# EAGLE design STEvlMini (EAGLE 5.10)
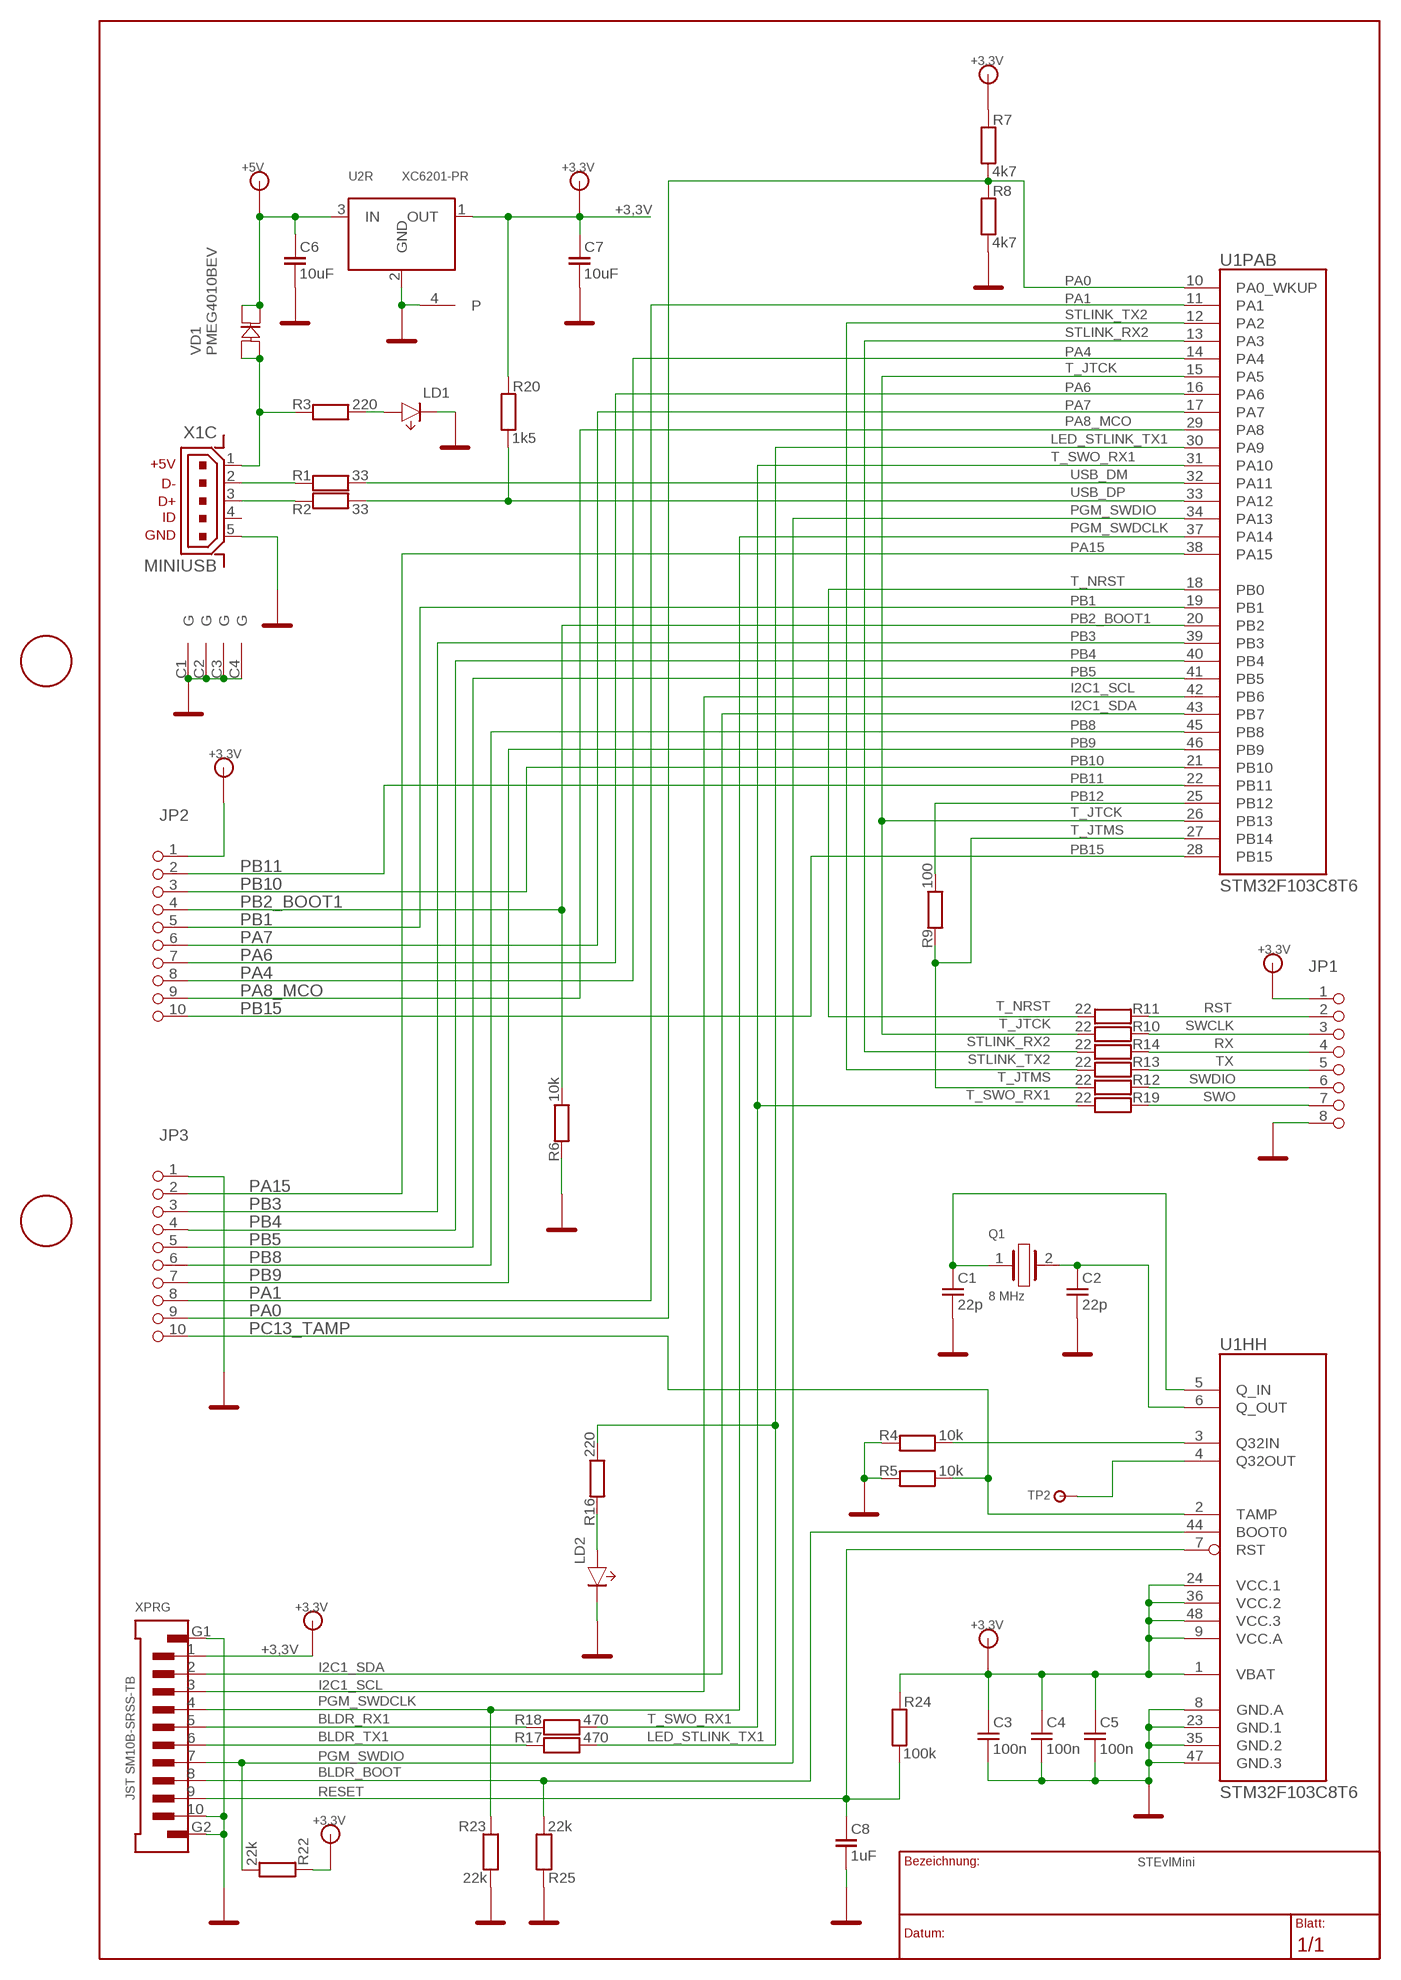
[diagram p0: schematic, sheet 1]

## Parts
C1  22p  SMD-0603  [SOT-0603]
C2  22p  SMD-0603  [SOT-0603]
C3  100n  SMD-0603  [SOT-0603]
C4  100n  SMD-0603  [SOT-0603]
C5  100n  SMD-0603  [SOT-0603]
C6  10uF  SMD-0805  [SOT-0805]
C7  10uF  SMD-0805  [SOT-0805]
C8  1uF  SMD-0805  [SOT-0805]
JP1  PINHD-1X8  [1X08]
JP2  PINHD-1X10'GERADE'  [1X10]
JP3  PINHD-1X10'GERADE'  [1X10]
LD1  LED0805  [LED0805]
LD2  LED0805  [LED0805]
Q1  8 MHz  XTAL'SMD5X3'  [XTAL5X3]
R1  33  SMD-0603  [SMD-0603]
R2  33  SMD-0603  [SMD-0603]
R3  220  SMD-0603  [SMD-0603]
R4  10k  SMD-0603  [SMD-0603]
R5  10k  SMD-0603  [SMD-0603]
R6  10k  SMD-0603  [SMD-0603]
R7  4k7  SMD-0603  [SMD-0603]
R8  4k7  SMD-0603  [SMD-0603]
R9  100  SMD-0603  [SMD-0603]
R10  22  SMD-0603  [SMD-0603]
R11  22  SMD-0603  [SMD-0603]
R12  22  SMD-0603  [SMD-0603]
R13  22  SMD-0603  [SMD-0603]
R14  22  SMD-0603  [SMD-0603]
R16  220  SMD-0603  [SMD-0603]
R17  470  SMD-0603  [SMD-0603]
R18  470  SMD-0603  [SMD-0603]
R19  22  SMD-0603  [SMD-0603]
R20  1k5  SMD-0603  [SMD-0603]
R22  22k  SMD-0603  [SMD-0603]
R23  22k  SMD-0603  [SMD-0603]
R24  100k  SMD-0603  [SMD-0603]
R25  22k  SMD-0603  [SMD-0603]
TP2  TESTPAD  [TESTPAD]
U1  STM32F103C8T6  [LQFP48]
U2  XC6201-PR  [SOT89]
VD1  PMEG4010BEV  [SOT23-6]
X1  MINIUSB  [UX60A-MB-5SY]
XPRG  JST SM10B-SRSS-TB  SR-10'H'  [SR-10H]

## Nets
+3,3V: C3.2 C4.2 C5.2 C7.2 JP1.1 JP2.1 R7.2 R20.2 R22.2 R24.2 U1.1(HH:VBAT) U1.9(HH:VCC.A) U1.24(HH:VCC.1) U1.36(HH:VCC.2) U1.48(HH:VCC.3) U2.1(R:OUT) XPRG.1
+5V: C6.2 U2.3(R:IN) VD1.1(K1) VD1.6(K)
BLDR_BOOT: R25.1 U1.44(HH:BOOT0) XPRG.8
BLDR_RX1: R18.1 XPRG.5
BLDR_TX1: R17.1 XPRG.6
GND: C1.1 C2.1 C3.1 C4.1 C5.1 C6.1 C7.1 C8.1 JP1.8 JP3.1 LD1.K LD2.K R4.2 R5.2 R6.2 R8.1 R23.1 R25.2 U1.8(HH:GND.A) U1.23(HH:GND.1) U1.35(HH:GND.2) U1.47(HH:GND.3) U2.2(R:GND) U2.4(P) X1.5 X1.C1(G) X1.C2(G) X1.C3(G) X1.C4(G) XPRG.10 XPRG.G1 XPRG.G2
I2C1_SCL: U1.42(PAB:PB6) XPRG.3
I2C1_SDA: U1.43(PAB:PB7) XPRG.2
LED_STLINK_TX1: R16.1 R17.2 U1.30(PAB:PA9)
N$1: R1.2 X1.2
N$2: R2.2 X1.3
N$4: C2.2 Q1.2 U1.6(HH:Q_OUT)
N$5: C1.2 Q1.1 U1.5(HH:Q_IN)
N$6: R4.1 U1.3(HH:Q32IN)
N$8: LD1.A R3.1
N$15: LD2.A R16.2
N$25: TP2.P$1(T) U1.4(HH:Q32OUT)
PA0: JP3.9 R7.1 R8.2 U1.10(PAB:PA0_WKUP)
PA1: JP3.8 U1.11(PAB:PA1)
PA4: JP2.8 U1.14(PAB:PA4)
PA6: JP2.7 U1.16(PAB:PA6)
PA7: JP2.6 U1.17(PAB:PA7)
PA8_MCO: JP2.9 U1.29(PAB:PA8)
PA15: JP3.2 U1.38(PAB:PA15)
PB1: JP2.5 U1.19(PAB:PB1)
PB2_BOOT1: JP2.4 R6.1 U1.20(PAB:PB2)
PB3: JP3.3 U1.39(PAB:PB3)
PB4: JP3.4 U1.40(PAB:PB4)
PB5: JP3.5 U1.41(PAB:PB5)
PB8: JP3.6 U1.45(PAB:PB8)
PB9: JP3.7 U1.46(PAB:PB9)
PB10: JP2.3 U1.21(PAB:PB10)
PB11: JP2.2 U1.22(PAB:PB11)
PB12: R9.1 U1.25(PAB:PB12)
PB15: JP2.10 U1.28(PAB:PB15)
PC13_TAMP: JP3.10 R5.1 U1.2(HH:TAMP)
PGM_SWDCLK: R23.2 U1.37(PAB:PA14) XPRG.4
PGM_SWDIO: R22.1 U1.34(PAB:PA13) XPRG.7
RESET: C8.2 R24.1 U1.7(HH:RST) XPRG.9
RST: JP1.2 R11.2
RX: JP1.4 R14.2
STLINK_RX2: R14.1 U1.13(PAB:PA3)
STLINK_TX2: R13.1 U1.12(PAB:PA2)
SWCLK: JP1.3 R10.2
SWDIO: JP1.6 R12.2
SWO: JP1.7 R19.2
T_JTCK: R10.1 U1.15(PAB:PA5) U1.26(PAB:PB13)
T_JTMS: R9.2 R12.1 U1.27(PAB:PB14)
T_NRST: R11.1 U1.18(PAB:PB0)
T_SWO_RX1: R18.2 R19.1 U1.31(PAB:PA10)
TX: JP1.5 R13.2
USB_DM: R1.1 U1.32(PAB:PA11)
USB_DP: R2.1 R20.1 U1.33(PAB:PA12)
USB_V5V: R3.2 VD1.3(A1) VD1.4(A) X1.1
Unconnected: X1.4

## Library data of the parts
C1-C5 = C_KERAM:SMD-0603
C6-C8 = C_KERAM:SMD-0805
JP1 = PINHD-Q:PINHD-1X8
JP2 JP3 = PINHD-Q:PINHD-1X10
LD1 LD2 = DIODEN:LED0805
Q1 = Z_SPECIA:XTAL
R1-R14 R16-R20 R22-R25 = R:SMD-0603
TP2 = Z_CONNEC:TESTPAD
U1 = SGS:STM32F103C8T6
U2 = TOREX:XC6201-PR
VD1 = DIODEN:PMEG4010BEV: Schottky, 40V, 1A
X1 = mini-usb:MINIUSB
XPRG = JST:SR-10

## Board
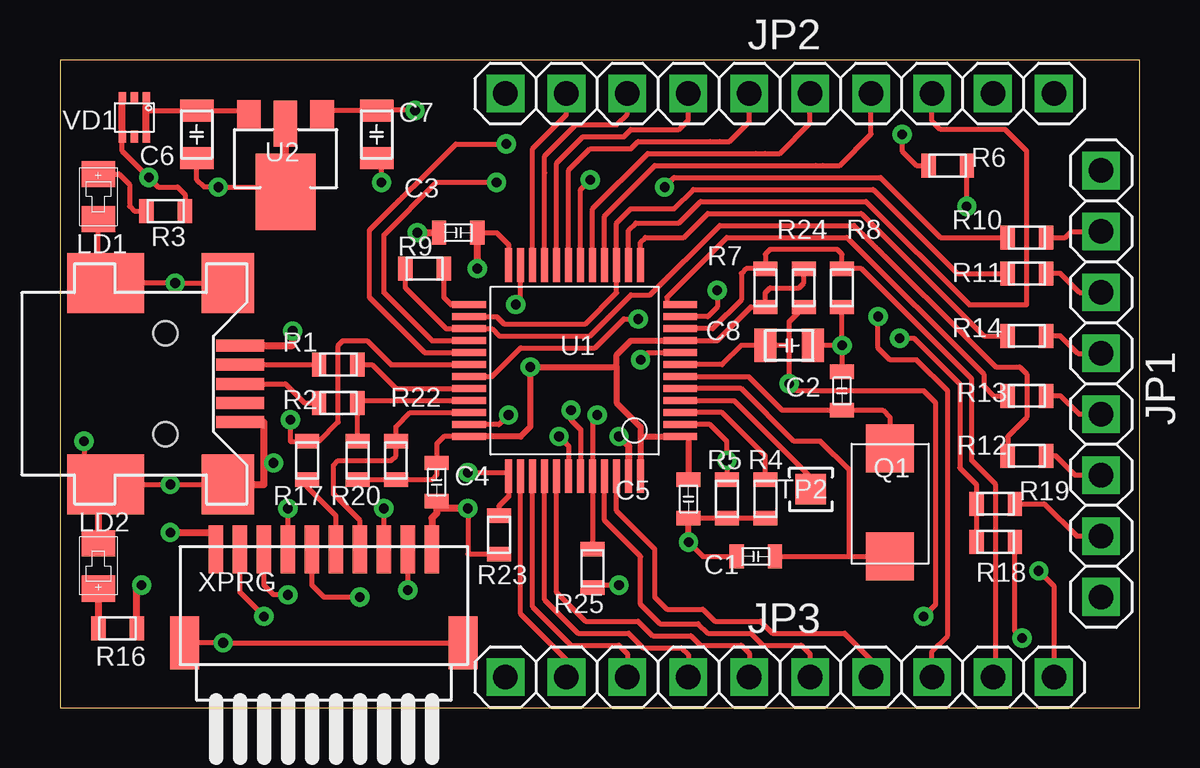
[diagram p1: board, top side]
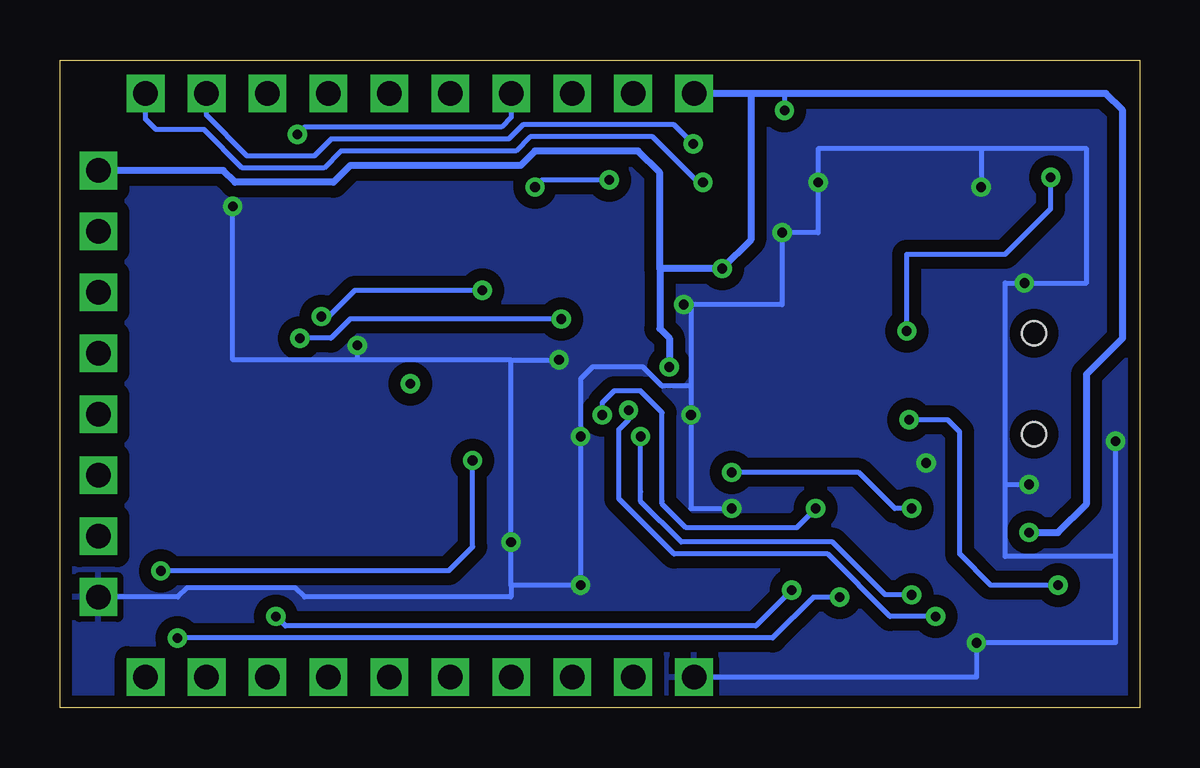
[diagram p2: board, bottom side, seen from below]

Size 45 x 27 mm. Coordinates in mm from the lower left corner, seen from the top.
Outline: 0,0 45,0 45,27 0,27 0,0
Copper layers (1*16): Top 0.035mm / dielectric 1.5mm / Bottom 0.035mm
Design rules "default *": minimum track width 0.15mm, minimum drill 0.3mm, track to track 0.15mm, track to pad 0.15mm, pad to pad 0.15mm, via to via 0.15mm, smd to smd 0mil, copper to edge 0.15mm, drill to drill 0.15mm, minimum pad ring 0.15mm, minimum via ring 0.15mm, stop-mask expansion 4mil, vias tented up to drill 0mil, thermal gap 10mil

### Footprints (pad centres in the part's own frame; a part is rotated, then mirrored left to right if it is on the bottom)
SOT-0603 = smd 0.6 x 1: 1 -0.8,0; 2 0.8,0
SOT-0805 = smd 0.914 x 1.397: 1 -0.991,0; 2 0.991,0
1X08 = drill 1.016 pad 1.575 square: 1 -8.89,0; 2 -6.35,0; 3 -3.81,0; 4 -1.27,0; 5 1.27,0; 6 3.81,0; 7 6.35,0; 8 8.89,0
1X10 = drill 1.016 pad 1.575 square: 1 -11.43,0; 2 -8.89,0; 3 -6.35,0; 4 -3.81,0; 5 -1.27,0; 6 1.27,0; 7 3.81,0; 8 6.35,0; 9 8.89,0; 10 11.43,0
LED0805 = smd 1.092 x 1.397: A 0.94,0; K -0.94,0
XTAL5X3 = smd 2 x 2: 1 -2.2,0; 2 2.3,0
SMD-0603 = smd 0.6 x 1: 1 -0.8,0; 2 0.8,0
TESTPAD = smd 1.27 x 1.27: P$1 0,0
LQFP48 = smd 0.28 x 1.4: 1 -2.75,-4.4; 2 -2.25,-4.4; 3 -1.75,-4.4; 4 -1.25,-4.4; 5 -0.75,-4.4; 6 -0.25,-4.4; 7 0.25,-4.4; 8 0.75,-4.4; 9 1.25,-4.4; 10 1.75,-4.4; 11 2.25,-4.4; 12 2.75,-4.4; 25 2.75,4.4; 26 2.25,4.4; 27 1.75,4.4; 28 1.25,4.4; 29 0.75,4.4; 30 0.25,4.4; 31 -0.25,4.4; 32 -0.75,4.4; 33 -1.25,4.4; 34 -1.75,4.4; 35 -2.25,4.4; 36 -2.75,4.4 | smd 1.4 x 0.28: 13 4.4,-2.75; 14 4.4,-2.25; 15 4.4,-1.75; 16 4.4,-1.25; 17 4.4,-0.75; 18 4.4,-0.25; 19 4.4,0.25; 20 4.4,0.75; 21 4.4,1.25; 22 4.4,1.75; 23 4.4,2.25; 24 4.4,2.75; 37 -4.4,2.75; 38 -4.4,2.25; 39 -4.4,1.75; 40 -4.4,1.25; 41 -4.4,0.75; 42 -4.4,0.25; 43 -4.4,-0.25; 44 -4.4,-0.75; 45 -4.4,-1.25; 46 -4.4,-1.75; 47 -4.4,-2.25; 48 -4.4,-2.75
SOT89 = smd 0.991 x 1.194: 1 -1.524,-1.829; 3 1.524,-1.829 | smd 0.991 x 1.905: 2 0,-1.448 | smd 2.5 x 3.2: 4 0,1.4
SOT23-6 = smd 0.3 x 0.5: 1 -0.5,-0.8; 2 0,-0.8; 3 0.5,-0.8; 4 0.5,0.8; 5 0,0.8; 6 -0.5,0.8
UX60A-MB-5SY = smd 0.5 x 2: 1 -1.6,3.1; 2 -0.8,3.1; 3 0,3.1; 4 0.8,3.1; 5 1.6,3.1 | smd 2.5 x 2.2: C1 -4.2,2.6; C4 4.2,2.6 | smd 2.5 x 3.2: C2 -4.2,-2.5; C3 4.2,-2.5 | hole 1.016: -2.1,0; 2.1,0
SR-10H = smd 0.6 x 2: 1 -4.5,2.4; 2 -3.5,2.4; 3 -2.5,2.4; 4 -1.5,2.4; 5 -0.5,2.4; 6 0.5,2.4; 7 1.5,2.4; 8 2.5,2.4; 9 3.5,2.4; 10 4.5,2.4 | smd 1.2 x 2.2: G1 -5.8,-1.5; G2 5.8,-1.5

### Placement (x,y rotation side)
C1  29,6.3 0 top
C2  32.6,13.2 270 top
C3  16.6,19.8 0 top
C4  15.7,9.4 90 top
C5  26.2,8.7 90 top
C6  5.7,23.9 90 top
C7  13.2,23.9 90 top
C8  30.4,15.1 180 top
JP1  43.4,13.5 270 top
JP2  30,25.6 0 top
JP3  30,1.27 0 top
LD1  1.6,21.3 90 top
LD2  1.6,5.9 270 top
Q1  34.6,8.5 90 top
R1  11.6,14.3 180 top
R2  11.6,12.7 180 top
R3  4.41,20.7 0 top
R4  29.4,8.7 270 top
R5  27.8,8.7 270 top
R6  37,22.6 0 top
R7  29.4,17.5 270 top
R8  32.6,17.5 90 top
R9  15.2,18.3 180 top
R10  40.3,18.1 0 top
R11  40.3,19.6 0 top
R12  40.3,10.5 0 top
R13  40.3,13 0 top
R14  40.3,15.5 0 top
R16  2.4,3.3 180 top
R17  10.3,10.3 90 top
R18  39,6.9 180 top
R19  39,8.5 0 top
R20  12.4,10.3 270 top
R22  14,10.3 270 top
R23  18.3,7.2 90 top
R24  31,17.5 90 top
R25  22.2,5.8 270 top
TP2  31.3,9.1 0 top
U1  21.45,14.05 90 top
U2  9.4,22.9 180 top
VD1  3.1,24.6 180 top
X1  4.4,13.5 270 top
XPRG  11,4.2 0 top

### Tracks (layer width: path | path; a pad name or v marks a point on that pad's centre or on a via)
+3,3V  (via drill 0.4 pad 0.8)
  Top 0.2: U1.9 27.4,15.3 28.8,16.7 R7.2 29.4,17.3 29.6,17.5 30.8,17.5 31,17.7 R24.2 | R20.2 R22.2 15.5,9.5 15.7,9.7 C4.2 15.7,11 16,11.3 U1.36 | U1.24 18.7,19.3 18.2,19.8 C3.2 | U2.1 10.92,24.89 C7.2 v14.8,24.9
  Top 0.25: 24.2,11.3 24.2,11.7 23.2,12.7 23.2,14.2 | 24.2,11.3 U1.1 26.2,11.3 C5.2 | 23.2,14.2 23.2,14.7 23.8,15.3 U1.9 | 24.2,11.3 U1.48 | U1.36 19.2,11.3 19.6,11.7 19.6,12.4 v19.6,14.2 23.2,14.2
  Top 0.3: XPRG.1 6.5,7.3 v4.6,7.3 | v17.4,18.3 C3.2
  Bottom 0.2: 14.8,25.6 v14.8,24.9
  Bottom 0.3: v4.6,7.3 3.4,7.3 2.2,8.5 2.2,13.9 0.7,15.4 0.7,24.9 1.4,25.6 14.8,25.6 16.2,25.6 | 20,18.3 20,15.8 19.6,15.4 v19.6,14.2 | 20,18.3 v17.4,18.3 16.2,19.5 16.2,25.6 | 16.2,25.6 JP2.1 | JP1.1 38.19,22.39 37.7,21.9 33.6,21.9 32.9,22.6 25.8,22.6 25.2,23.2 20.9,23.2 20,22.3 20,18.3
+5V
  Top 0.2: U2.3 7.88,24.89 C6.2 3.6,24.89 VD1.1
  Top 0.3: VD1.6 VD1.1
BLDR_BOOT  (via drill 0.4 pad 0.8)
  Top 0.2: R25.1 U1.44 22.2,12 v22.4,12.2 | XPRG.8 v13.5,8.3
  Bottom 0.2: v13.5,8.3 14.3,7.5 18.9,7.5 19.9,8.5 19.9,8.6 19.9,12.3 20.8,13.2 21.9,13.2 22.4,12.7 v22.4,12.2
BLDR_RX1  (via drill 0.4 pad 0.8)
  Top 0.2: XPRG.5 10.5,5.1 11,4.6 v12.5,4.6 | v40.1,2.9 39.8,3.2 R18.1
  Bottom 0.2: v12.5,4.6 13.6,4.6 15.3,2.9 v40.1,2.9
BLDR_TX1
  Top 0.2: XPRG.6 11.5,8 10.3,9.2 R17.1
GND  (via drill 0.4 pad 0.8)
  Top 0.2: C5.1 R5.2 R4.2 | U1.8 24.5,14.8 v24.2,14.5 | v32.6,15.1 C8.1 | v32.6,15.1 R8.1 | C1.1 26.8,6.3 v26.2,6.9 | X1.C3 1.6,9.3 1.6,8.75 | XPRG.G1 v6.8,2.7 XPRG.G2 | v1,11.1 1,9.3 X1.C3 | 1.6,17.7 LD1.K | X1.C1 v4.8,17.7 X1.C2 | X1.C3 v4.6,9.3 X1.C4 | 8.5,11.9 X1.5 | U1.35 18.3,11.8 v18.7,12.2 | U1.23 19.2,17 v19,16.8 | R25.2 22.2,5.1 v23.3,5.1 | v32.6,15.1 C2.1 | R23.1 17,6.4 v17,8.3 | C6.1 5.7,22 6,21.7 v6.6,21.7 9.4,21.7 U2.4 | v37.8,20.9 R6.2 | C7.1 13.4,22.71 v13.4,21.9
  Top 0.25: v26.2,6.9 C5.1
  Top 0.3: 1.6,8.75 LD2.K | X1.C2 1.6,17.7 | X1.C4 8.5,9.3 8.5,10.2 | 8.5,10.2 8.5,11.9 | U2.4 U2.2 | v14.9,19.8 C3.1 | XPRG.10 15.5,7.9 15.7,8.1 15.7,8.3 | 8.5,10.2 v8.9,10.2 | U1.47 23.7,10.9 v23.3,11.3 | 15.7,8.3 C4.1 | v17,8.3 15.7,8.3
  Bottom 0.2: 26.2,14.5 v24.2,14.5 | 26.2,14.5 C5.1 v26.2,6.9 26.2,5.1 | 26.2,14.5 32.6,14.5 | 1,6.3 1,2.7 v6.8,2.7 6.8,1.27 JP3.1 | 1,6.3 v1,11.1 | 5.6,9.3 v4.6,9.3 | 5.6,9.3 5.6,6.3 1,6.3 | 5.6,9.3 5.6,17.7 v4.8,17.7 2.2,17.7 2.2,23.3 6.6,23.3 | v17,8.3 18.7,8.3 v18.7,12.2 18.7,13.4 | 18.7,13.4 18.7,16.8 v19,16.8 14.9,16.8 v14.9,19.8 13.4,19.8 v13.4,21.9 13.4,22.4 13.4,23.3 6.6,23.3 | 26.2,5.1 v23.3,5.1 v23.3,11.3 23.3,13.7 22.8,14.2 20.7,14.2 19.9,13.4 18.7,13.4 | JP1.8 40.09,4.61 39.7,5 35.2,5 34.81,4.61 26.2,4.61 26.2,5.1 | 6.6,23.3 v6.6,21.7 | v37.8,20.9 37.8,14.5 32.6,14.5 | 32.6,14.5 v32.6,15.1
  pour Bottom (isolate 0.5): 0.3,26.6 0.3,0.4 44.6,0.4 44.6,26.6
I2C1_SCL  (via drill 0.4 pad 0.8)
  Top 0.2: XPRG.3 8.5,5.1 8.9,4.7 v9.5,4.7 | U1.42 21.2,10.8 21.2,10.9 v20.8,11.3
  Bottom 0.2: v9.5,4.7 10.6,4.7 12.8,6.9 19.1,6.9 20.8,8.6 20.8,9 v20.8,11.3
I2C1_SDA  (via drill 0.4 pad 0.8)
  Top 0.2: XPRG.2 7.5,4.8 v8.5,3.8 | v21.3,12.4 21.3,12 21.7,11.6 U1.43
  Bottom 0.2: v8.5,3.8 10.4,3.8 13,6.4 19.4,6.4 21.7,8.7 21.7,9.1 21.7,11.6 21.3,12 v21.3,12.4
LED_STLINK_TX1  (via drill 0.4 pad 0.8)
  Top 0.2: U1.30 13.8,14.3 12.8,15.3 11.8,15.3 11.6,15.1 11.6,11.9 10.8,11.1 R17.2 9.6,11.1 v9.6,12
  Top 0.3: R16.1 3.2,4.9 v3.4,5.1
  Bottom 0.2: v3.4,5.1 6.2,5.1 7.5,6.4 7.5,11.5 8,12 v9.6,12
N$1
  Top 0.2: X1.2 R1.2
N$2
  Top 0.2: X1.3 9.4,13.5 10.2,12.7 R2.2
N$4
  Top 0.2: U1.6 28.7,13.8 30.1,12.4 C2.2 34.3,12.4 34.6,12.1 Q1.2
N$5
  Top 0.2: C1.2 32.9,6.3 | U1.5 28.4,13.3 30.6,11.1 31.7,11.1 32.9,9.9 32.9,6.3 | 32.9,6.3 Q1.1
N$6
  Top 0.2: U1.3 27.6,12.3 29.4,10.5 R4.1
N$8
  Top 0.2: R3.1 3.1,20.7 2.9,20.9 2.9,21.8 2.46,22.24 LD1.A
N$15
  Top 0.3: LD2.A R16.2
N$25
  Top 0.2: U1.4 28.1,12.8 31.3,9.6 TP2.P$1
PA0
  Top 0.2: U1.10 27.2,15.8 28.4,17 28.4,18.1 28.6,18.3 R7.1 29.4,18.9 29.6,19.1 32.4,19.1 32.6,18.9 R8.2 33.4,18.3 38,13.7 38,10.3 39,9.3 39,1.38 JP3.9
PA1  (via drill 0.4 pad 0.8)
  Top 0.2: U1.11 27,16.3 27.4,16.7 v27.4,17.4 | v34.1,16.3 34.1,15 34.6,14.5 35.7,14.5 37,13.2 37,3 36.35,2.35 JP3.8
  Bottom 0.2: v27.4,17.4 32.7,17.4 33.8,16.3 v34.1,16.3
PA4
  Top 0.2: U1.14 23.7,19.9 24,20.2 25.8,20.2 26.7,21.1 33.6,21.1 37.9,16.8 40.3,16.8 40.3,21.1 40.3,22 40.3,23.2 39.4,24.1 36.7,24.1 36.35,24.45 JP2.8
PA6
  Top 0.2: U1.16 22.7,20.5 24.8,22.6 31.5,22.6 31.8,22.6 32.5,22.6 33.81,23.91 JP2.7
PA7
  Top 0.2: U1.17 22.2,20.8 24.5,23.1 29,23.1 29.4,23.1 30,23.1 31.27,24.37 JP2.6
PA8_MCO  (via drill 0.4 pad 0.8)
  Top 0.2: U1.29 15.2,14.8 12.9,17.1 12.9,19.9 16.5,23.5 v18.6,23.5
  Bottom 0.2: v18.6,23.5 19.4,24.3 25.7,24.3 26.3,23.7 33.7,23.7 34.4,23 37.2,23 38.89,24.69 JP2.9
PA15
  Top 0.2: U1.38 19.2,3.9 21.11,1.99 JP3.2
PB1
  Top 0.2: U1.19 21.2,22.4 22.1,23.3 23.8,23.3 24.1,23.6 27.1,23.6 27.5,23.6 27.9,23.6 28.73,24.43 JP2.5
PB2_BOOT1  (via drill 0.4 pad 0.8)
  Top 0.2: JP2.4 26.19,24.49 25.8,24.1 23.8,24.1 23.5,23.8 21.8,23.8 20.7,22.7 U1.20 | v35.1,23.9 35.1,23.2 35.7,22.6 R6.1
  Bottom 0.2: JP2.4 26.19,24.61 26.6,24.2 34.8,24.2 v35.1,23.9
PB3
  Top 0.2: U1.39 19.7,4.2 21.3,2.6 23.3,2.6 23.65,2.25 JP3.3
PB4
  Top 0.2: U1.40 20.2,4.5 21.6,3.1 23.7,3.1 24.3,2.5 25.9,2.5 26.19,2.21 JP3.4
PB5
  Top 0.2: U1.41 20.7,4.8 21.9,3.6 24.1,3.6 24.7,3 26.3,3 26.7,2.6 28.4,2.6 28.73,2.27 JP3.5
PB8
  Top 0.2: U1.45 22.7,7.8 24.2,6.3 24.2,4.3 25,3.5 26.6,3.5 27,3.1 28.8,3.1 29.3,2.6 30.9,2.6 31.27,2.23 JP3.6
PB9
  Top 0.2: U1.46 23.2,8.2 24.8,6.6 24.8,4.6 25.3,4.1 26.8,4.1 27.3,3.6 29.2,3.6 29.7,3.1 32.7,3.1 33.81,1.99 JP3.7
PB10
  Top 0.2: U1.21 20.2,22.3 20.2,23 21.5,24.3 23.2,24.3 23.65,24.75 JP2.3
PB11
  Top 0.2: U1.22 19.7,23.3 21.11,24.71 JP2.2
PB12
  Top 0.2: U1.25 16.3,16.8 16,17.1 R9.1
PB15  (via drill 0.4 pad 0.8)
  Top 0.2: U1.28 15.5,15.3 13.5,17.3 13.5,19.7 15.7,21.9 v18.2,21.9
  Bottom 0.2: v18.2,21.9 18.4,21.9 20.3,23.8 25.4,23.8 26,23.2 33.3,23.2 34,22.5 37.4,22.5 39,24.1 41,24.1 41.43,24.53 JP2.10
PC13_TAMP  (via drill 0.4 pad 0.8)
  Top 0.2: U1.2 27.1,11.8 27.8,11.1 v27.8,10.3 R5.1 | JP3.10 41.43,5.07 v40.8,5.7
  Bottom 0.2: v27.8,10.3 27.8,6.7 28.8,5.7 v40.8,5.7
PGM_SWDCLK  (via drill 0.4 pad 0.8)
  Top 0.2: XPRG.4 v9.5,8.3 | v17,9.8 18.7,9.8 U1.37 18.7,8.8 18.3,8.4 R23.2
  Bottom 0.2: v9.5,8.3 10.2,8.3 11.7,9.8 v17,9.8
PGM_SWDIO
  Top 0.2: U1.34 14.6,12.3 14,11.7 R22.1 14,10.5 13.8,10.3 11.6,10.3 11.4,10.1 11.4,8.9 12.5,7.8 XPRG.7
RESET  (via drill 0.4 pad 0.8)
  Top 0.2: U1.7 27.6,14.3 28.4,15.1 C8.2 30.4,15.1 | 30.4,15.1 30.4,16.1 R24.1 | 30.4,15.1 v30.4,13.5 30.7,13.2 36,13.2 36.5,12.7 36.5,4.3 v36,3.8 | v14.5,4.9 XPRG.9
  Bottom 0.2: v14.5,4.9 16,3.4 35.6,3.4 v36,3.8
RST
  Top 0.2: JP1.2 42.15,19.85 41.9,19.6 R11.2
RX
  Top 0.2: JP1.4 42.43,14.77 41.7,15.5 R14.2
STLINK_RX2
  Top 0.2: R14.1 38.5,15.5 33.4,20.6 27,20.6 26,19.6 24.4,19.6 24.2,19.4 U1.13
STLINK_TX2
  Top 0.2: U1.12 25.3,16.8 25.3,17.1 27.8,19.6 32.8,19.6 38.5,13.9 38.5,13.4 38.9,13 R13.1
SWCLK
  Top 0.2: JP1.3 42.49,17.31 41.7,18.1 R10.2
SWDIO
  Top 0.2: JP1.6 42.31,9.69 41.5,10.5 R12.2
SWO
  Top 0.2: R19.2 41.03,8.5 42.38,7.15 JP1.7
T_JTCK
  Top 0.2: U1.26 18.2,16.3 18.5,16 21.9,16 23.2,17.3 U1.15 23.2,20.2 23.8,20.8 25.6,20.8 26.4,21.6 33.9,21.6 37.4,18.1 R10.1
T_JTMS
  Top 0.2: R9.2 14.4,17.5 16.1,15.8 U1.27 18,15.8 18.3,15.5 22.1,15.5 23.8,17.2 24.6,17.2 27.5,20.1 33.1,20.1 39,14.2 40,14.2 40.3,13.9 40.3,12.1 39.5,11.3 R12.1
T_NRST  (via drill 0.4 pad 0.8)
  Top 0.2: U1.18 21.7,21.6 v22.1,22 | v25.2,21.7 25.6,22.1 34.2,22.1 36.7,19.6 R11.1
  Bottom 0.2: v22.1,22 24.9,22 v25.2,21.7
T_SWO_RX1  (via drill 0.4 pad 0.8)
  Top 0.2: R18.2 R19.1 38.2,9.3 37.5,10 37.5,13.5 35.6,15.4 v35,15.4 | U1.31 18,13.8 19.2,15 22.3,15 23.5,16.2 v24.1,16.2
  Bottom 0.2: v24.1,16.2 32.9,16.2 33.7,15.4 v35,15.4
TX
  Top 0.2: JP1.5 42.47,12.23 41.7,13 R13.2
USB_DM
  Top 0.2: U1.32 14,13.3 13,14.3 R1.1
USB_DP
  Top 0.2: U1.33 12.5,12.8 R2.1 R20.1
USB_V5V  (via drill 0.4 pad 0.8)
  Top 0.2: VD1.4 2.6,23.2 v3.7,22.1 4.1,21.7 4.9,21.7 5.21,21.39 R3.2
  Top 0.3: X1.1 9.7,15.1 v9.7,15.7 | VD1.4 VD1.3
  Bottom 0.2: v9.7,15.7 9.7,18.9 5.6,18.9 3.7,20.8 v3.7,22.1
